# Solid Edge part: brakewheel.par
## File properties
Author: KULL
Template: Iso Metric Part.par
Last saved by: KULL
Revision: 6
Application: Solid Edge
Accuracy: 0,990
Face Style: Model Default
Fill Style: Normal
Coef. of Thermal Exp: 0.0
Thermal Conductivity: 0.0
Specific Heat: 0.0
Modulus of Elasticity: 0.0
Poisson's Ratio: 0.0
Yield Stress: 0.0
Ultimate Stress: 0.0
Elongation: 0.0
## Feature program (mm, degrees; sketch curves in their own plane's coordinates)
pattern "unnamed Pattern 1"
Other named dimensions: "Pattern_2": XOffset = 20 deg
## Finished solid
Body 1: solid body, 544 faces, 1066 edges, 432 vertices.
  Faces by surface: torus 226, cylinder 204, blend 72, plane 42
  Edges by curve: circle 742, intersection 216, line 108
Bounding box of the edges (mm; curved faces can reach further): 52.000 x 5.000 x 52.000, from (-26, 118, -3) to (26, 123, 49).
Cylindrical faces by radius (mm): R0.2 x36, R0.7 x36, R0.8 x36, R0.9 x36, R4 x1, R10 x2, R14.7173 x18, R15 x2, R17 x18, R26 x1, R28.4 x18
Toroidal faces (ring radius, tube radius in mm): R0.8 r0.1 x36, R0.9 r0.1 x36, R1 r0.1 x36, R9.8 r0.2 x2, R10.2 r0.2 x2, R14.8 r0.2 x2, R15.1173 r0.4 x36, R15.2 r0.2 x2, R25.8 r0.2 x38, R28 r0.4 x36
Planar faces by outward normal: +y 21, -y 21
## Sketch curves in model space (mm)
circle centre (0, 122, 23) radius 10
circle centre (0, 122, 23) radius 4
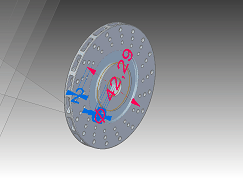
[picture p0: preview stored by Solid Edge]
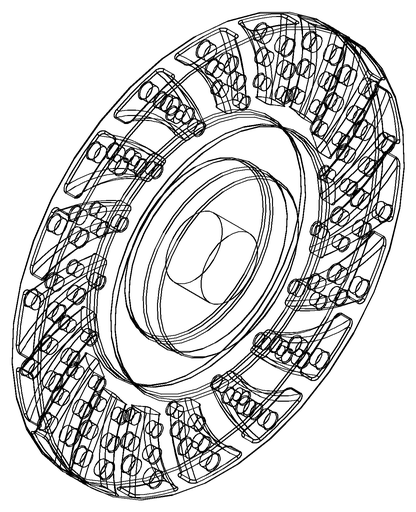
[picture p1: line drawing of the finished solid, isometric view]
